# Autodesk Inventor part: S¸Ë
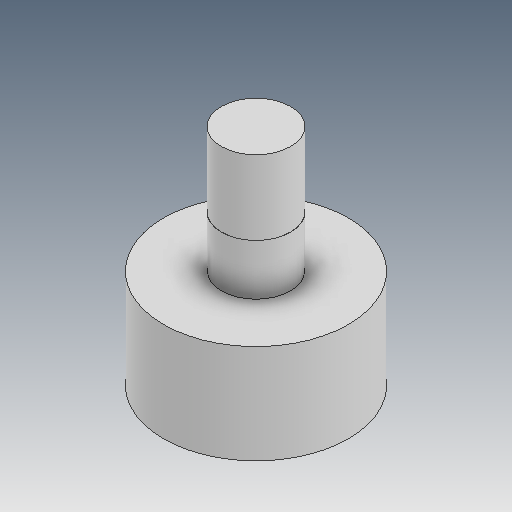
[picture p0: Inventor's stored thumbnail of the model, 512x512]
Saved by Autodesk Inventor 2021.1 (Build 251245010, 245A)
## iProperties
Created: 2019-04
Part Number: S¸Ë
Material: Ogólny
Document SubType Name: Modeling
Designer: user
Density: 1 g/cm^3
Appearance: Domyślna
Author: user
Revision Number: ÈÎºÎ
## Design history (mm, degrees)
feature "Ðý×ª1"
node "Bryła1"
